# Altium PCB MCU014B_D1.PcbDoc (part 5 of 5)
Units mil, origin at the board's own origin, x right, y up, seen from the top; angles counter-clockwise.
Board outline 2300.04 x 4058 mil, 4 copper layers (TOP, GND, PWR, BOTTOM), stack 48.84 mil thick; 371 components, 238 nets, 1148 pads, 688 vias.
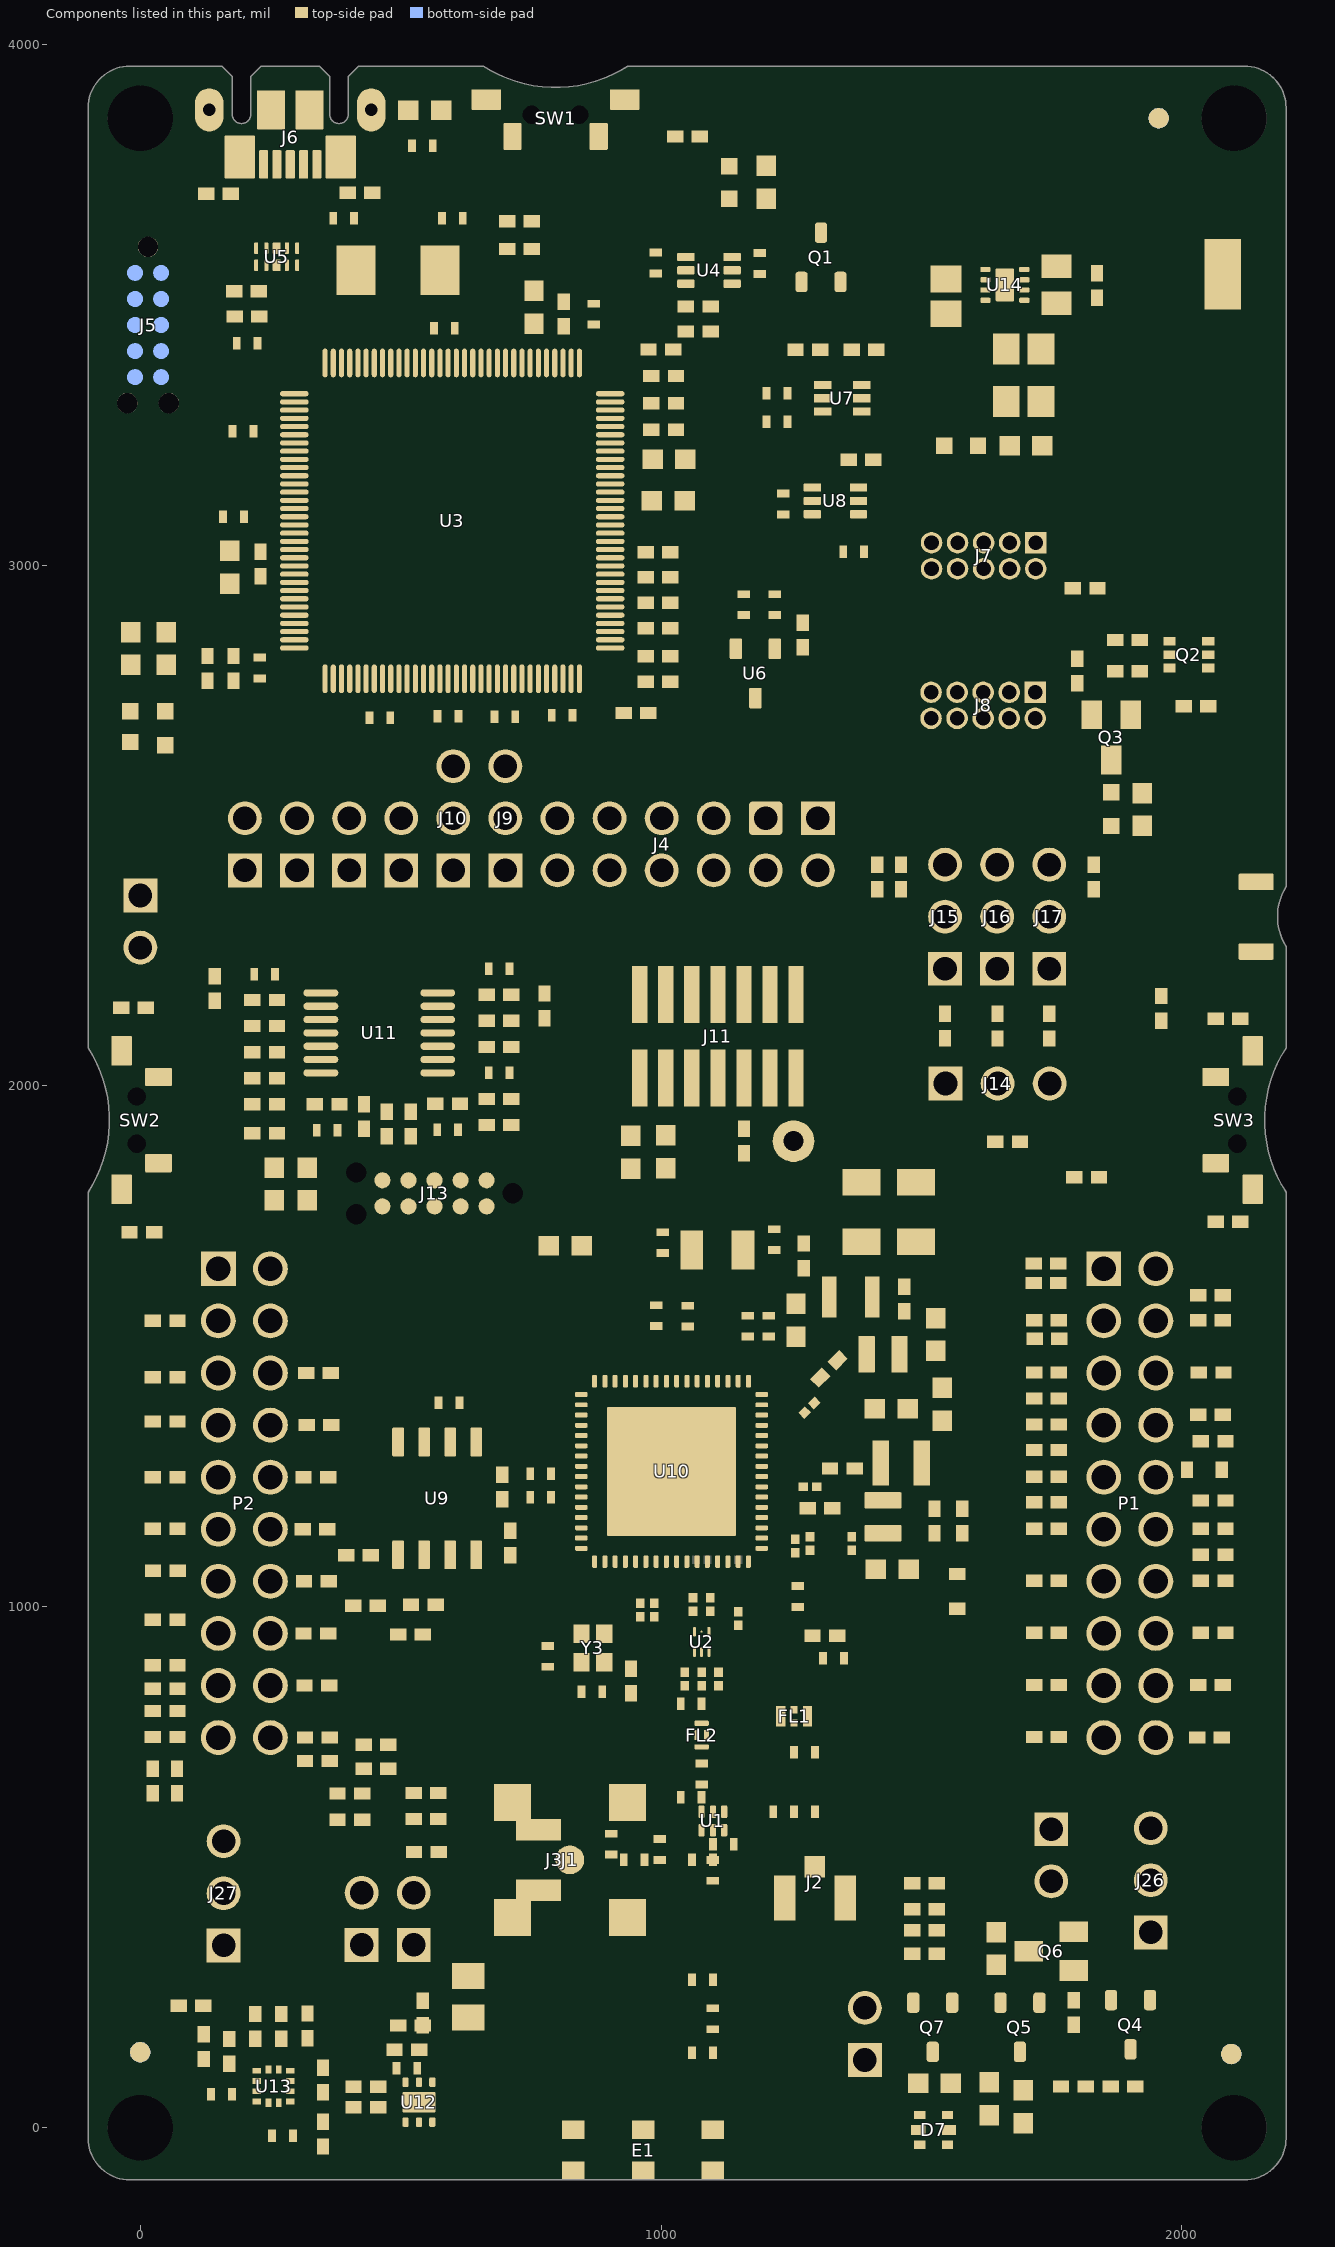
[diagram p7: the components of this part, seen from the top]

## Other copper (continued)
BOTTOM:
  pour cut-out: 729.61,-100.02 772.5,-100.02 772.5,75.2 729.61,75.2
  pour cut-out: 749.56,330.93 761.13,319.37 1068.87,319.37 1068.87,378.37 749.56,378.37
  pour cut-out: 1068.87,323.73 1077.25,332.11 1077.25,369.99 1068.87,378.37
  pour cut-out: 862.43,282.25 862.43,217.85 885.01,195.27 1183.98,195.27 1186.09,197.38 1186.09,263.32 1168.89,280.53 1080.35,280.53 1062.71,298.17 878.35,298.17
  pour cut-out: 1090.33,496.78 1120.32,466.79 1181.55,466.79 1219.5,504.74 1098.29,504.74
  pour cut-out: 1018.6,732.85 1018.6,725.94 1030.04,714.49 1211.05,714.49 1211.05,746.79 1032.54,746.79
  pour cut-out: 1329,595.38 1329,557.41 1477.45,557.41 1483.29,563.26 1483.29,594.76 1474.26,603.79 1337.41,603.79
  pour cut-out: 343.52,1718.81 343.52,1689.22 355.34,1677.4 371.61,1677.4 384.45,1690.24 384.45,1717.67 376.92,1725.19 349.9,1725.19
  pour cut-out: 1399.31,2354.95 1399.31,2325.35 1411.13,2313.53 1427.4,2313.53 1440.24,2326.37 1440.24,2353.8 1432.71,2361.33 1405.69,2361.33
  pour cut-out: 40.82,949.77 40.82,920.18 52.64,908.36 68.91,908.36 81.75,921.2 81.75,948.62 74.22,956.15 47.2,956.15
  pour cut-out: 293.71,917.28 293.71,887.68 305.53,875.86 321.81,875.86 334.64,888.7 334.64,916.13 327.12,923.66 300.09,923.66
  pour cut-out: 705.57,2688.96 705.57,2658.96 713.24,2651.28 735.89,2651.28 742.1,2657.5 742.1,2681.97 730.78,2693.3 709.91,2693.3
  pour cut-out: 601.74,2704.6 601.74,2693.15 603.14,2691.75 622.46,2691.75 624.4,2693.69 624.4,2705.18 622,2707.58 604.72,2707.58
  pour cut-out: 596,1359 596,1537 809,1750 1575,1750 1646,1679 1646,1550 1616,1520 823,1520 661,1358 594,1358
  pour cut-out: 452.71,2851.1 460.19,2851.1 460.19,2836.9 452.71,2836.9
  pour cut-out: 1087.7,3310.6 1086.15,3318.4 1081.73,3325.02 1075.11,3329.44 1067.31,3330.99 1059.51,3329.44 1052.89,3325.02 1048.47,3318.4 1046.92,3310.6 1048.47,3302.79 1052.89,3296.18 1059.51,3291.76 1067.31,3290.2 1075.11,3291.76 1081.73,3296.18 1086.15,3302.79
  pour cut-out: 152 vertices and 0 holes, not listed, extent 1872.45,1006 1927.55,1089
  pour cut-out: 2000.35,911.1 1987.07,911.1 1986.2,911.14 1985.33,911.26 1984.48,911.45 1983.65,911.71 1982.84,912.04 1982.07,912.44 1981.33,912.91 1980.64,913.44 1980,914.03 1979.41,914.68 1978.88,915.37 1978.41,916.1 1978.01,916.88 1977.67,917.68 1977.41,918.52 1977.22,919.37 1977.11,920.23 1977.07,921.1 1977.11,921.98 1977.22,922.84 1977.41,923.69 1977.67,924.52 1978.01,925.33 1978.41,926.1 1978.88,926.84 1979.18,927.25 1981.05,929.88 1982.69,932.67 1984.07,935.58 1985.2,938.61 1986.06,941.72 1986.65,944.89 1986.95,948.1 1986.98,951.33 1986.72,954.55 1986.18,957.73 1985.37,960.86 1984.29,963.9 1982.95,966.83 1981.81,968.89 1981.4,969.66 1981.06,970.46 1980.78,971.29 1980.58,972.14 1980.46,973.01 1980.41,973.88 1980.44,974.75 1980.54,975.61 1980.72,976.47 1980.97,977.3 1981.3,978.11 1981.69,978.89 1982.15,979.63 1982.67,980.33 1983.25,980.98 1983.89,981.58 1984.57,982.12 1985.3,982.6 1986.07,983.01 1986.88,983.35 1987.7,983.63 1988.55,983.83 1989.42,983.95 1990.29,984 1990.41,984 2004.56,984 2081.93,1061.37 2082.57,1061.96 2083.26,1062.49 2084,1062.96 2084.77,1063.36 2085.58,1063.7 2086.41,1063.96 2087.26,1064.15 2088.13,1064.26 2089,1064.3 2089.87,1064.26 2090.74,1064.15 2091.59,1063.96 2092.42,1063.7 2093.23,1063.36 2094,1062.96 2094.74,1062.49 2095.43,1061.96 2096.07,1061.37 2096.66,1060.73 2097.19,1060.04 2097.66,1059.3 2098.06,1058.53 2098.4,1057.72 2098.66,1056.89 2098.85,1056.04 2098.96,1055.17 2099,1054.3 2099,1009.76 2000.35,911.1
  pour cut-out: 1912.93,911.1 1887.07,911.1 1886.2,911.14 1885.33,911.26 1884.48,911.45 1883.65,911.71 1882.84,912.04 1882.07,912.44 1881.33,912.91 1880.64,913.44 1880,914.03 1879.41,914.68 1878.88,915.37 1878.41,916.1 1878.01,916.88 1877.67,917.68 1877.41,918.52 1877.22,919.37 1877.11,920.23 1877.07,921.1 1877.11,921.98 1877.22,922.84 1877.41,923.69 1877.67,924.52 1878.01,925.33 1878.41,926.1 1878.88,926.84 1879.18,927.25 1881.05,929.88 1882.69,932.67 1884.07,935.58 1885.2,938.61 1886.06,941.72 1886.65,944.89 1886.95,948.1 1886.98,951.33 1886.72,954.55 1886.18,957.73 1885.37,960.86 1884.29,963.9 1882.95,966.83 1881.81,968.89 1881.4,969.66 1881.06,970.46 1880.78,971.29 1880.58,972.14 1880.46,973.01 1880.41,973.88 1880.44,974.75 1880.54,975.61 1880.72,976.47 1880.97,977.3 1881.3,978.11 1881.69,978.89 1882.15,979.63 1882.67,980.33 1883.25,980.98 1883.89,981.58 1884.57,982.12 1885.3,982.6 1886.07,983.01 1886.88,983.35 1887.7,983.63 1888.55,983.83 1889.42,983.95 1890.29,984 1890.41,984 1909.59,984 1910.46,983.96 1911.33,983.85 1912.18,983.66 1913.01,983.4 1913.82,983.06 1914.59,982.66 1915.33,982.19 1916.02,981.66 1916.66,981.07 1917.25,980.43 1917.78,979.74 1918.25,979 1918.65,978.23 1918.99,977.42 1919.25,976.59 1919.44,975.74 1919.55,974.87 1919.59,974 1919.55,973.13 1919.44,972.26 1919.25,971.41 1918.99,970.58 1918.65,969.77 1918.25,969 1918.19,968.89 1916.66,966.05 1915.39,963.08 1914.38,960.02 1913.64,956.87 1913.18,953.68 1913,950.46 1913.1,947.23 1913.49,944.02 1914.15,940.86 1915.08,937.77 1916.28,934.78 1917.73,931.9 1919.43,929.15 1920.82,927.25 1921.32,926.54 1921.77,925.79 1922.14,925 1922.45,924.18 1922.68,923.34 1922.84,922.49 1922.92,921.62 1922.92,920.74 1922.86,919.88 1922.71,919.01 1922.49,918.17 1922.2,917.35 1921.84,916.56 1921.41,915.8 1920.91,915.08 1920.36,914.41 1919.74,913.78 1919.08,913.22 1918.37,912.71 1917.62,912.27 1916.83,911.9 1916.01,911.59 1915.17,911.36 1914.31,911.2 1913.44,911.12 1912.93,911.1
  pour cut-out: 772.5,75.2 1054,75.2 1054,55.51 1146.52,55.51 1146.52,-100 772.5,-100
  pour cut-out: 471.93,3737.96 471.93,3721.48 481.89,3711.52 493.38,3711.52 500.32,3718.45 500.32,3735.52 493.89,3741.94 475.91,3741.94
  pour cut-out: 855.47,3481.21 926.38,3410.31 927.21,3411.14 927.21,3449.21 895.21,3481.21
  pour cut-out: 752.7,732.69 1572.38,732.69 1626.28,786.59 1626.28,1102.59 1597.28,1131.59 1263.57,1131.59 1198.51,1066.52 794.35,1066.52 763.28,1097.59 763.28,1221.59 667.28,1317.59 475.28,1317.59 447.28,1289.59 447.28,1048.59 449.28,1046.59 555.28,1046.59 658.28,943.59 658.28,827.1
  pour cut-out: 312.92,3719.89 319.36,3713.45 319.36,3703.69 307.96,3703.69 298.7,3712.94
  pour cut-out: 1364.58,387.11 1364.58,372.4 1357.16,364.97 1093.98,364.97 1080.58,378.37 823.89,378.37 823.89,430.76 1320.5,431.51
  pour cut-out: 601.53,1754.19 601.53,1721.33 619.67,1703.19 633.2,1703.19 646.96,1716.95 646.96,1751.84 636.88,1761.92 609.27,1761.92
  pour cut-out: 618.75,1848.64 613.97,1843.87 625.17,1832.67 629.31,1836.8
  pour cut-out: 279.01,1933.2 279.01,1910.06 302.5,1886.58 313.73,1886.58 328.54,1901.38 328.54,1935.33 319.09,1944.78 290.6,1944.78
  pour cut-out: 1030.64,329.76 1346.3,329.77 1355.49,338.95 1355.49,359.47 1339.12,375.83 1076.71,375.83
  pour cut-out: 1336.2,702.3 1361.47,702.3 1372.62,713.45 1372.62,746.16 1336.2,746.16
  text "4" at 141.62,-60.43 h50
  text ".layer_Name" at -466,-1142 h60

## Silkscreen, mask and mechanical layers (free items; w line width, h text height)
Top Silkscreen:
  drawing of 7084 lines, arcs and shapes, not listed
  text "RESET" at 1087.18,3867.5 h30
  text "RESET" at 745.24,3720.11 h30
  text "GND" at 2038.69,3700.4 h30
  text "REV B" at 1341.44,3668.74 h30
  text "3V3" at 1526.59,3314.45 h30
  text "XDS110" at 1538.35,3161.97 h30
  text "OUT" at 1580.83,3125.63 h30
  text "CAUTION" at -77.89,3029.21 h30
  text "HOT" at -23.39,2981.11 h30
  text "SURFACE" at -81.39,2938.51 h30
  text "JTAG IN" at 1523.26,2848.71 h30
  text "VCC_BUFFER" at 1333.67,2584.19 h30 r90
  text "2" at 1535.62,2489.21 h40
  text "1" at 1640,2489.21 h40
  text "0" at 1725,2489.21 h40
  text "PD" at 1419.37,2466.31 h30
  text "FRST" at 1982.9,2457.44 h30
  text "TX" at 723.21,2296.35 h30 r90
  text "RX" at 622.21,2293.21 h30 r90
  text "5V" at 321.61,2271.91 h30 r90
  text "BRD" at 513,2266.5 h30 r90
  text "RST" at 821,2266.5 h30 r90
  text "TMS" at 927.21,2267.21 h30 r90
  text "TCK" at 1026,2266.79 h30 r90
  text "BRD" at 1322,2266.5 h30 r90
  text "TDI" at 1223.88,2266.41 h30 r90
  text "TDO" at 1120.69,2265.26 h30 r90
  text "GND" at 221.01,2251.51 h30 r90
  text "SOP" at 1464.55,2235.88 h40 r90
  text "VBAT" at 420.91,2227.21 h30 r90
  text "OPAMP EN" at 107.81,2208.21 h30 r90
  text "PU" at 1418.13,2179.33 h30
  text "(P15)" at 1820.66,2120.87 h30
  text "ET POD" at 916,1997 h30 r90
  text "SOP VCC" at 1299.54,1979.67 h30
  text "P4" at 1749.87,1714.73 h40
  text "P2" at 1972.04,1714.73 h40
  text "20" at 1913.35,1704.94 h30
  text "40" at 1827.63,1702.15 h30
  text "P1" at 79,1701 h40
  text "P3" at 277,1701 h40
  text "1" at 157,1700 h35
  text "21" at 207,1700 h35
  text "*" at 1688.11,1689.02 h30
  text "P02" at 1600.91,1664.91 h30
  text "P58" at 1599.36,1616.17 h30
  text "P18" at 2110.69,1577.16 h30
  text "*" at 1688.11,1567.97 h30
  text "*" at -17,1549 h30
  text "P01" at 1609.1,1547.44 h30
  text "P59" at 2110.19,1533.59 h30
  text "P58" at -87.26,1521.22 h30
  text "P50" at 1603.97,1496.14 h30
  text "*" at 1673.3,1436.5 h30
  text "P57" at 395,1435 h30
  text "P08" at 2106.71,1432.41 h30
  text "P04" at -87.94,1425.68 h30
  text "P17" at 1605.89,1411.79 h30
  text "*" at 1679.06,1352.14 h30
  text "P45" at 2105.31,1347.91 h30
  text "P03" at -88.6,1338.29 h30
  text "P60" at 395,1335 h30
  text "P64" at 1609.61,1329.6 h30
  text "*" at 1676.52,1245.2 h30
  text "RST" at 2113.56,1240.96 h30
  text "P58" at 386.57,1235.76 h30
  text "P61" at -84.58,1233.57 h30
  text "P21" at 1605.35,1228.92 h30
  text "*" at 1670.24,1161.86 h30
  text "*" at -13.55,1143.19 h30
  text "P59" at 385,1135 h30
  text "P18" at 1611.05,1135.04 h30
  text "P07" at 2108.11,1135.21 h30
  text "P59" at -86.29,1122.41 h30
  text "*" at 1680.67,1059.85 h30
  text "P05" at -85.24,1054.82 h30
  text "P62" at 1609.47,1035.24 h30
  text "P06" at 2110.91,1034.41 h30
  text "P63" at 390.11,1032.51 h30
  text "*" at 1665.51,966.71 h30
  text "P62" at -84.75,966.46 h30
  text "P60" at 1605.36,936.77 h30
  text "P21" at 2112.51,933.81 h30
  text "P53" at 390.64,930.95 h30
  text "P55" at 2103.91,833.71 h30
  text "P64" at 395,830 h30
  text "P01" at -67.49,828.81 h30
  text "P16" at 1605.41,827 h30
  text "P17" at 1605.41,738 h30
  text "P02" at -76.62,737.36 h30
  text "P15" at 2105.71,732.11 h30
  text "RF" at 624.83,706.53 h30
  text "11" at 1879.53,680.05 h35
  text "31" at 1785.14,676.24 h35
  text "10" at 125,666 h35
  text "30" at 215,665 h35
  text "P50" at 274.67,632.4 h30
  text "RF" at 1388.45,519.57 h30
  text "RST PU" at 1675.61,456.38 h30 r90
  text "(SCL)" at 340.79,450.17 h30 r90
  text "(SDA)" at 643.34,448.76 h30 r90
  text "LED EN" at 1311.6,150.26 h30 r90
  text "SENSORS" at 98.26,30.9 h30 r90
  text "GREEN->P02" at 1198.48,13.1 h30
  text "TEMP" at 647.32,-20.61 h30 r90
  text "RED  ->P01" at 1198.48,-34.33 h30
  text "ACC" at 127.25,-70.69 h30
  text "BLUE ->P64" at 1198.48,-81.76 h30
  text ".layer_Name" at -466,-1142 h60
Bottom Silkscreen:
  drawing of 11597 lines, arcs and shapes, not listed
  text "SimpleLink™  CC3235 Launchpad™" at 1472.95,3347.07 h90
  text "Development Kit" at 1472.95,3217.94 h90
  text "MCU014" at 467.21,3049.24 h50
  text "www.ti.com/launchpad" at 1477.14,3034.17 h90
  text "REV B" at 476.18,3007.12 h50
  text "SOP (2:0)" at 453.18,2912.19 h60
  text "XDS110 OUT" at 1747.23,2893.94 h45
  text "100  :  FLASH" at 453.19,2843.99 h60
  text "000  :  4W JTAG" at 457.59,2781.85 h60
  text "001  :  2W SWD" at 457.04,2721.9 h60
  text "010  :  FLASH/FUNC" at 457.04,2656.46 h60
  text "JTAG IN" at 1700.13,2624.28 h45
  text "VCC_BUFFER" at 1292.85,2580.18 h45 r270
  text "TX" at 691.51,2294.41 h30 r270
  text "RX" at 596.81,2286.61 h30 r270
  text "TMS" at 892,2277 h30 r270
  text "TDO" at 1088.18,2266.21 h30 r270
  text "TDI" at 1190.82,2266.08 h30 r270
  text "BRD" at 1286.21,2266.21 h30 r270
  text "BRD" at 484.21,2264.61 h30 r270
  text "5V" at 290.21,2264.21 h30 r270
  text "TCK" at 989,2262 h30 r270
  text "RST" at 792,2261 h30 r270
  text "GND" at 190.71,2254.21 h30 r270
  text "SOP" at 1425.42,2235.27 h40 r270
  text "VBAT" at 389.81,2226.61 h30 r270
  text "OPAMP EN" at 80.51,2208.91 h30 r270
  text "20" at 1954.13,1728.3 h30
  text "P1" at 110.3,1726.54 h40
  text "1" at 166.21,1727.21 h35
  text "21" at 265.21,1727.21 h35
  text "P3" at 367.66,1724.59 h40
  text "40" at 1884.34,1724.59 h30
  text "P2" at 2074.71,1719.35 h40
  text "P4" at 1787.13,1715.35 h40
  text "P02" at 1777,1632 h35
  text "P18" at 2102,1537 h35
  text "P01" at 1777,1532 h35
  text "P58" at 85.31,1529.61 h31
  text "P08" at 2105,1435 h35
  text "P57" at 403.01,1431.61 h35
  text "P17" at 1777,1432 h35
  text "P04" at 79.21,1427 h35
  text "P60" at 399.21,1340.91 h35
  text "P45" at 2106,1334 h35
  text "P64" at 1777,1331 h35
  text "P03" at 79.21,1327 h35
  text "P58" at 400.71,1243.31 h35
  text "P21" at 1777,1234 h35
  text "RST" at 2099,1234 h35
  text "P61" at 79.21,1227 h35
  text "P07" at 2102.91,1136.61 h35
  text "P59" at 399.21,1132.71 h35
  text "P18" at 1777,1133 h35
  text "P59" at 90.3,1126.83 h33
  text "P62" at 1777,1037 h35
  text "P06" at 2096,1036 h35
  text "P05" at 79.21,1027 h35
  text "P63" at 398.41,1025.21 h35
  text "P21" at 2100,934 h35
  text "P60" at 1777,933 h35
  text "P62" at 79.21,927 h35
  text "P53" at 404.31,919.01 h35
  text "P64" at 404.11,835.01 h35
  text "P55" at 2100,834 h35
  text "P16" at 1777,830 h35
  text "P01" at 79.21,827 h35
  text "P50" at 398.91,735.01 h35
  text "P15" at 2100,734 h35
  text "P17" at 1776.21,733.21 h35
  text "P02" at 79.21,727 h35
  text "30" at 271.6,635 h35
  text "11" at 1962.41,635.01 h35
  text "31" at 1868.51,634.21 h35
  text "10" at 165.6,633 h35
  text "RST PU" at 1645.62,456.38 h30 r270
  text "SDA" at 564.49,251.53 h30
  text "SCL" at 457.69,249.15 h30
  text "LED EN" at 1286.23,103.43 h30 r270
  text ".layer_Name" at -466,-1142 h60
Top Paste:
  text ".layer_Name" at -468,-1140 h60
Bottom Paste:
  text ".layer_Name" at -468,-1140 h60
Top Solder:
  text ".layer_Name" at -468,-1140 h60
Bottom Solder:
  text ".layer_Name" at -468,-1140 h60
Drill Guide:
  text ".layer_Name" at -466,-1142 h60
M1  Board Outline:
  the board outline again, w10
  text ".layer_Name" at -466,-1142 h60
M2 Board Dimensions:
  rectangle: -868.53,-701.56 -493.53,-576.56
  rectangle: -993.53,-576.56 -868.53,-451.56
  lines w7: -993.53,-576.56 6.47,-576.56 ; -868.53,-701.56 -868.53,-451.56 ; -743.53,-701.56 -743.53,-451.56 ; -493.53,-701.56 -493.53,-451.56 ; -243.53,-701.56 -243.53,-451.56 ; -993.53,-701.56 6.47,-701.56 6.47,-451.56 -993.53,-451.56 -993.53,-701.56
  text "2 PLACES" at 434.6,4117.7 h30
  text "4 PLACES" at 2352.65,3764.25 h30
  text "3 PLACES" at -656,1984.21 h60
  text ".layer_Name" at -466,-1142 h60
M3 3D STEP Top:
  pour cut-out: 1580,1720 1580,960 1155,960 1155,990 1120,1025 1035,1025 1000,990 1000,910 935,910 935,805 925,795 655,795 655,1720 1580,1720
AST:
  circle w10: c1268.67,3521.79 r8.25
  circle w10: c949.12,3865.14 r4
  circle w10: c2112.01,1778.81 r4
  circle w10: c-11.09,2085.81 r4
  circle w6: c78,346 r10
  circle w6: c1073.53,1668 r4.47
  circle w6: c178.9,2345.23 r7.21
  circle w6: c278.9,2345.23 r7.21
  circle w6: c378.9,2345.23 r7.21
  circle w6: c478.9,2345.23 r7.21
  circle w6: c578.9,2345.23 r7.21
  circle w6: c678.9,2345.23 r7.21
  circle w6: c1230.46,2584.78 r7.21
  circle w6: c1265.98,2583.27 r7.21
  circle w6: c1718.28,2755.78 r7.21
  circle w6: c1818.21,589.21 r7.21
  circle w10: c1218.4,2797.6 r8.06
  circle w6: c1073.53,1668 r4.47
  circle w6: c78,346 r10
  circle w10: c359.25,3563.2 r8.25
  circle w6: c1705.27,2156.93 r7.21
  circle w6: c1605.27,2156.93 r7.21
  circle w6: c1505.27,2156.93 r7.21
  circle w6: c1258.25,2134.13 r10
  circle w6: c1476.73,1969.77 r7.21
  circle w6: c1599.96,1908.01 r7.21
  circle w6: c1915.46,2716.43 r10
  circle w6: c1719.19,3043.01 r10
  circle w10: c1124.97,156.27 r3.29
  rectangle: 1816.76,1615.95 1883.12,1682.11
  rectangle: 116.75,1615.95 183.12,1682.11
  lines w10: -1274.5,-1223.17 5325.5,-1223.17 ; -1274.5,-1019.83 5327.5,-1019.83 ; -1274.5,-816.5 -1274.5,-1426.5 2730.5,-1426.5 5327.5,-1426.5 5327.5,-816.5 -1274,-816.5 -1274,-1426.5 301.5,-1426.5 ; 525.58,-1017.28 525.58,-816.88 ; 1116.99,-101.97 1116.99,16.14 ; 1190.5,-1426.5 1190.5,-1020.28 ; 2457.5,-1019.83 2457.5,-816.5 ; 3297.5,-1019.83 3297.5,-816.5 ; 3919.5,-1433 3919.5,-1230.17
  text "R63" at 1786.55,1813.5 h25
  text "PCB VIEWED FROM TOP SIDE" at -1211,-948.67 h60
  text "BOARD #:" at 565.5,-948.67 h60
  text ".PRJ_Title" at 1111,-948.67 h60
  text "REV:" at 2655.5,-948.67 h60
  text ".PCB_Rev" at 2947,-948.67 h60
  text "SVN REV:" at 3493.5,-948.67 h60
  text ".VersionControl_RevNumber" at 3999.5,-948.67 h60
  text "COMPONENTS MARKED 'DNP' SHOULD NOT BE POPULATED." at 1222.98,-1099.51 h35
  text "TOP ASSEMBLY DRAWING" at -1211,-1151.49 h60
  text "ASSEMBLY VARIANT:" at 1233.73,-1181.89 h35
  text ".VariantName" at 1828.34,-1185.48 h35
  text "GENERATED    :" at 1267.5,-1357.34 h60
  text ".Print_Date" at 2137,-1357.34 h60
  text ".Print_Time" at 2866,-1357.34 h60
  text "TEXAS INSTRUMENTS" at 4130.5,-1357.34 h60
ASB:
  lines w10: -1275,-1020.33 5327,-1020.33 ; -1273,-1223.67 5327,-1223.67 ; 133,-1433.5 133,-1230.67 ; 755,-1020.33 755,-817 ; 1595,-1020.33 1595,-817 ; 2862,-1427 2862,-1020.26 ; 3633.38,-1019.37 3633.38,-815.76 ; 3751,-1427 5326.5,-1427 5326.5,-817 -1275,-817 -1275,-1427 1322,-1427 5327,-1427 5327,-817
  text ".VersionControl_RevNumber" at 53,-949.17 h60
  text "SVN REV:" at 559,-949.17 h60
  text ".PCB_Rev" at 1105.5,-949.17 h60
  text "REV:" at 1397,-949.17 h60
  text "PCB VIEWED FROM BOTTOM SIDE" at 5263.5,-949.17 h60
  text ".PRJ_title" at 3062.64,-951.18 h60
  text "BOARD #:" at 3553.68,-951.18 h60
  text "COMPONENTS MARKED 'DNP' SHOULD NOT BE POPULATED." at 2838.45,-1092.34 h35
  text "BOTTOM ASSEMBLY DRAWING" at 5263.5,-1153.5 h60
  text ".VariantName" at 2175.78,-1174.74 h35
  text "ASSEMBLY VARIANT:" at 2831.29,-1181.89 h35
  text "TEXAS INSTRUMENTS" at -78,-1357.84 h60
  text ".Print_Time" at 1186.5,-1357.84 h60
  text ".Print_Date" at 1915.5,-1357.84 h60
  text "GENERATED    :" at 2785,-1357.84 h60
Route Tool Path:
  drawing of 57 lines, arcs and shapes, not listed
  text "1" at -253.7,7734.94 h70
  text "2" at 2241.97,7734.94 h70
  text "3" at 4731.31,7734.94 h70
  text "4" at 7237.98,7734.94 h70
  text "5" at 9736.97,7734.94 h70
  text "6" at 12241.97,7734.94 h70
  text "A" at -1410.03,6591.94 h70
  text "A" at 13389.97,6591.94 h70
  text "B" at -1410.03,4211.94 h70
  text "B" at 13389.97,4211.94 h70
  text "C" at -1410.03,1836.94 h70
  text "C" at 13389.97,1836.94 h70
  text "PROJECT TITLE:" at 10349.97,-24.06 h45
  text ".PRJ_Title" at 10399.97,-157.38 h70
  text "DESIGNED FOR:" at 10349.97,-325.06 h45
  text ".PRJ_Customer" at 10399.97,-465.06 h70
  text "D" at -1410.03,-533.06 h70
  text "D" at 13389.97,-533.06 h70
  text "FILE NAME:" at 10349.97,-625.06 h45
  text ".PCB_File_Name_No_Path" at 10399.97,-745.06 h70
  text "Texas Instruments (TI) and/or its licensors do not warrant the accuracy or completeness of this specification" at 5380.47,-906.9 h45
  text "ENGINEER:" at 10349.97,-915.06 h45
  text "LAYOUT BY:" at 11854.97,-915.06 h45
  text "or any information contained therein. TI and/or its licensors do not warrant that this design will meet" at 5335.48,-1019.56 h45
  text ".PRJ_Engineer" at 10399.97,-1070.05 h70
  text ".PCB_Layout" at 11905.47,-1070.05 h70
  text "the specifications, will be suitable for your application or fit for any particular purpose, or will operate in" at 5335.48,-1132.23 h45
  text ".layer_Name" at -466,-1142 h60
  text "ALTIUM DESIGNER VERSION:" at 11854.97,-1225.06 h45
  text "an implementation. TI and/or its licensors do not warrant that the design is production worthy. You should" at 5335.48,-1244.89 h45
  text "completely validate and test your design implementation to confirm the system functionality for your application." at 5380.47,-1357.56 h45
  text ".print_Scale" at 10399.97,-1358.38 h70
  text ".Application_BuildNumber" at 11905.47,-1358.38 h70
  text "1" at -253.7,-1565.06 h70
  text "2" at 2241.97,-1565.06 h70
  text "3" at 4731.31,-1565.06 h70
  text "4" at 7237.98,-1565.06 h70
  text "5" at 9736.97,-1565.06 h70
  text "6" at 11302.71,-1565.06 h70
  text "WO# : 307170-7168-1DU" at 11753.54,-1565.06 h70
M10 Fab Notes:
  drawing of 213 lines, arcs and shapes, not listed
  text "FAB NOTES :" at -1133.5,7542.43 h65
  text "1. EXPOSED COPPER ARE PRESENT AT BOARD EDGE IN ALL ELECTRICAL LAYERS AT THE LOCATION \"DETAIL A\". copper in that area must be as close to the edge as current processing allows" at -1129.88,7372.9 h65
  text "2. THE SOLDER MASK IMAGES THAT ARE THE SAME SIZE AS THE COMPONENT PADS MAY BE ENLARGED AS PER THE MANUFACTURING CAPABILITIES." at -1129.88,7214.17 h65
  text "ALL OTHER SOLDER MASK IMAGES SHALL NOT BE MODIFIED." at -936.12,7098.21 h65
  text "DESIGN INFORMATION" at 11387.49,6143.44 h60
  text "MIN. TRACK WIDTH:" at 10742.93,5963.44 h60
  text "MIL" at 11993.93,5963.44 h60
  text "6" at 11835,5962 h60
  text "4" at 11833.1,5833.96 h60
  text "MIN. CLEARANCE:" at 10742.93,5831.44 h60
  text "MIL" at 11993.93,5831.44 h60
  text "MIN. VIA PAD SIZE:" at 10742.93,5699.44 h60
  text "18" at 11809.18,5699.45 h60
  text "MIL" at 11993.93,5699.44 h60
  text "EXTERNAL" at 12288.21,5559.21 h60
  text "2 MIL" at 11437.93,5557.73 h60
  text "MINIMUM ANNULAR RING" at 10413.7,5553.45 h60
  text "PER" at 10613.7,5435.45 h60
  text "IPC-D-275 CLASS 2 LEVEL C" at 10833.7,5435.44 h60
  text "MIL, HOLES" at 12321.93,5323.16 h60
  text "+/-" at 11929.47,5322.44 h60
  text "+/-" at 12783.47,5322.44 h60
  text "REGISTRATION TOLERANCES:" at 10413.7,5317.44 h60
  text "METAL" at 11613.47,5317.44 h60
  text "5" at 12189.67,5317.45 h60
  text "3" at 13022.67,5317.45 h60
  text "MIL" at 13138.93,5317.44 h60
  text "MATERIAL:" at 10338.93,5107.98 h60
  text "FR-4 High Tg" at 11325.37,4967.65 h60
  text "FR-408" at 10759.93,4959.08 h60
  text "X" at 11171.93,4959.08 h60
  text "OTHER" at 12247.93,4959.08 h60
  text "1.28mm+/-10%" at 12644.58,4799.21 h60
  text "62 MIL (1.6mm) +/-10%" at 11080.03,4796.37 h60
  text "THICKNESS:" at 10413.7,4792.08 h60
  text "X" at 12246.86,4792.08 h60
  text "OTHER" at 12344.93,4792.08 h60
  text "TOLERANCE:" at 10413.7,4634.08 h60
  text "X" at 11253,4634.08 h60
  text "ANSI IPC-6012 TYPE 3 CLASS 2" at 11439.94,4634.08 h60
  text "OTHER +/-" at 11439.93,4478.08 h60
  text "BOW & TWIST:" at 10413.7,4321.08 h60
  text "X" at 11253,4321.08 h60
  text "ANSI IPC-6012 TYPE 3 CLASS 2" at 11439.94,4321.08 h60
  text "OTHER +/-" at 11439.93,4162.57 h60
  text "COPPER THICKNESS (FINISHED):" at 10392.46,3906.14 h60
  text "1.4MIL (1oz)" at 12644.46,3758.42 h60
  text "INNER SIGNAL:" at 11832.38,3754.14 h60
  text "X" at 12517.42,3754.14 h60
  text "1.4MIL (1oz)" at 11272.46,3753.42 h60
  text "OUTER:" at 10749.46,3749.14 h60
  text "X" at 11144,3748.5 h60
  text "DRILLING:" at 10338.93,3489.08 h60
  text "REFERENCE:" at 10413.7,3372.08 h60
  text "X" at 11061.93,3372.08 h60
  text "AS SHOWN" at 11248.93,3372.08 h60
  text "X" at 11962.93,3372.08 h60
  text "NC_DRILL FILES" at 12099.93,3372.08 h60
  text "PTH MIN COPPER THICKNESS:" at 10413.7,3214.08 h60
  text "X" at 11763.93,3214.08 h60
  text "1MIL" at 11900.93,3214.08 h60
  text "OTHER" at 12397.93,3214.08 h60
  text "BOARD FINISH:" at 10338.93,3055.08 h60
  text "SILKSCREEN:" at 10494.15,2937.08 h60
  text "X" at 11442.93,2937.08 h60
  text "TOP" at 11568.93,2937.08 h60
  text "X" at 11952.93,2937.08 h60
  text "BOTTOM" at 12079.93,2937.08 h60
  text "SILKSCREEN COLOR:" at 10494.15,2770.08 h60
  text "X" at 11441.89,2770.08 h60
  text "WHITE" at 11568.93,2770.08 h60
  text "OTHER" at 12079.93,2770.08 h60
  text "SOLDER RESIST COLOR:" at 10494.15,2600.08 h60
  text "X" at 12166.89,2445.88 h60
  text "GREEN" at 11188.93,2440.88 h60
  text "BLUE" at 11779.93,2440.88 h60
  text "OTHER" at 12317.93,2440.88 h60
  text "RED" at 12707.93,2435.88 h60
  text "IMMERSION GOLD (ENIG)" at 11399.93,2252.37 h60
  text "ENEPIG" at 12737.47,2249.08 h60
  text "SURFACE FINISH:" at 10338.93,2248.08 h60
  text "X" at 11212.98,2248.08 h60
  text "IMM. TIN/SILVER OR EQUIV" at 10668.47,2091.08 h60
  text "OTHER" at 12099.93,2091.08 h60
  text "ARRAY/PANEL:" at 10338.93,1912.08 h60
  text "CUT AND TRIM PER MECH LAYER 1" at 11399.93,1907.8 h60
  text "N.C. ROUTE" at 11399.93,1756.08 h60
  text "V. SCORE" at 12265.93,1756.08 h60
  text "X" at 11209.99,1755.17 h60
  text "CERTIFICATION:" at 10338.93,1619.08 h60
  text "MATERIALS AND WORKMANSHIP FOR ALL PCBS" at 11063.93,1619.08 h60
  text "TO MEET OR EXCEED THE REQUIREMENTS OF:" at 11063.93,1521.08 h60
  text "X" at 10690.43,1384.58 h60
  text "ANSI IPC-A-600F CLASS ->" at 10829.43,1384.58 h60
  text "X" at 12468.49,1384.58 h60
  text "2" at 12587.43,1384.58 h60
  text "1" at 12272.43,1383.08 h60
  text "3" at 12941.43,1383.08 h60
  text "X" at 10692.49,1225.08 h60
  text "UL 94V-0" at 10829.43,1225.08 h60
  text "X" at 11504.49,1225.08 h60
  text "RoHS" at 11641.43,1225.08 h60
  text "OTHER" at 12285.83,1225.08 h60
  text "PER ORDER" at 12682.89,1225.08 h60
  text "ADDITIONAL REQUIREMENTS:" at 10338.93,1084.08 h60
  text "X" at 12320.49,985.08 h60
  text "YES" at 12456.43,983.08 h60
  text "NO" at 12910.43,983.08 h60
  text "VIA TENTING:" at 11561,978 h60
  text "MICROSECTION:" at 10413.7,969.08 h60
  text "YES" at 11319.43,969.08 h60
  text "REQUIRED" at 12180.93,812.94 h60
  text "BARE BOARD ELEC. TEST:" at 10413.7,810.08 h60
  text "NONE" at 11719.43,810.08 h60
  text "X" at 12053.93,810.08 h60
  text "PER ORDER" at 12772.93,810.08 h60
  text "MANUFACTURER'S UL:" at 10413.7,653.08 h60
  text "RAIL" at 11579.43,648.8 h60
  text "METAL" at 12071.24,648.8 h60
  text "SILK" at 12582.93,648.8 h60
  text "X" at 12446.47,648.44 h60
  text ".layer_Name" at -466,-1142 h60
M11 Gerber Information:
  lines w10: -1285.53,-1231.72 5314.47,-1231.72 ; -1285.53,-1028.39 5316.47,-1028.39 ; -1285.53,-825.06 -1285.53,-1435.06 2719.47,-1435.06 5316.47,-1435.06 5316.47,-825.06 -1285.03,-825.06 -1285.03,-1435.06 290.47,-1435.06 ; 704.27,-1028.98 704.27,-826.22 ; 1179.47,-1435.06 1179.47,-1027.64 ; 2647.88,-1028.62 2647.88,-825.28 ; 3286.47,-1028.39 3286.47,-825.06 ; 3908.47,-1441.56 3908.47,-1238.72
  text ".PCB_Rev" at 2968.73,-956.1 h60
  text "ALL ARTWORK VIEWED FROM TOP SIDE" at -1222.03,-957.22 h60
  text "BOARD #:" at 747.56,-957.22 h60
  text ".PRJ_title" at 1293.06,-957.22 h60
  text "REV:" at 2702.69,-956.74 h60
  text "SVN REV:" at 3482.47,-957.22 h60
  text ".VersionControl_RevNumber" at 3988.47,-957.22 h60
  text "LAYER NAME =" at -1222.03,-1140 h60
  text "GENERATED    :" at 1256.47,-1365.89 h60
  text ".Print_Date" at 2125.97,-1365.89 h60
  text ".Print_Time" at 2854.97,-1365.89 h60
  text "TEXAS INSTRUMENTS" at 4119.47,-1365.89 h60
M12 Stackup:
  drawing of 306 lines, arcs and shapes, not listed
  text "LAYER STACKUP" at 4664.28,3466.47 h125
  text "Layer" at 3408.27,3247.73 h60
  text "Name" at 3818.18,3247.73 h60
  text "Material" at 4917.87,3247.73 h60
  text "Thickness" at 5777.64,3247.73 h60
  text "Constant" at 6427.48,3247.73 h60
  text "Board Layer Stack" at 6997.34,3247.73 h60
  text "1" at 3408.27,3127.73 h60
  text "Top Silkscreen" at 3818.18,3127.73 h60
  text "2" at 3408.27,3007.73 h60
  text "Top Solder" at 3818.18,3007.73 h60
  text "Solder Resist" at 4917.87,3007.73 h60
  text "0.80mil" at 5777.64,3007.73 h60
  text "4.1" at 6427.48,3007.73 h60
  text "3" at 3408.27,2887.73 h60
  text "TOP" at 3818.18,2887.73 h60
  text "Copper" at 4917.87,2887.73 h60
  text "1.69mil" at 5777.64,2887.73 h60
  text "4" at 3408.27,2767.73 h60
  text "Dielectric1" at 3818.18,2767.73 h60
  text "FR-4 High Tg" at 4917.87,2767.73 h60
  text "9.30mil" at 5777.64,2767.73 h60
  text "3.9" at 6427.48,2767.73 h60
  text "5" at 3408.27,2647.73 h60
  text "GND" at 3818.18,2647.73 h60
  text "Copper" at 4917.87,2647.73 h60
  text "1.42mil" at 5777.64,2647.73 h60
  text "6" at 3408.27,2527.73 h60
  text "Dielectric2" at 3818.18,2527.73 h60
  text "FR-4 High Tg" at 4917.87,2527.73 h60
  text "24.02mil" at 5777.64,2527.73 h60
  text "4.24" at 6427.48,2527.73 h60
  text "7" at 3408.27,2407.73 h60
  text "PWR" at 3818.18,2407.73 h60
  text "Copper" at 4917.87,2407.73 h60
  text "1.42mil" at 5777.64,2407.73 h60
  text "8" at 3408.27,2287.73 h60
  text "Dielectric3" at 3818.18,2287.73 h60
  text "FR-4 High Tg" at 4917.87,2287.73 h60
  text "9.30mil" at 5777.64,2287.73 h60
  text "3.9" at 6427.48,2287.73 h60
  text "9" at 3408.27,2167.73 h60
  text "BOTTOM" at 3818.18,2167.73 h60
  text "Copper" at 4917.87,2167.73 h60
  text "1.69mil" at 5777.64,2167.73 h60
  text "10" at 3408.27,2047.73 h60
  text "Bottom Solder" at 3818.18,2047.73 h60
  text "Solder Resist" at 4917.87,2047.73 h60
  text "0.80mil" at 5777.64,2047.73 h60
  text "4.1" at 6427.48,2047.73 h60
  text "11" at 3408.27,1927.73 h60
  text "Bottom Silkscreen" at 3818.18,1927.73 h60
  text "THIS IS AN IMPEDANCE CONTROLLED BOARD" at 3766.39,1661.2 h125
  text "NOTE : EXTERNAL LAYER CU THICKNESS ARE FINISHED THICKNESS AFTER PLATING." at 3528.79,1439.45 h75
  text "IMPEDANCE TABLE" at 4765.91,953.13 h125
  text "LAYER NO" at 3566.52,625.77 h70
  text "CONDUCTOR WIDTH" at 4212.04,625.77 h70
  text "SPACING" at 5289.85,625.77 h70
  text "IMPEDANCE +/-10%" at 5877.1,625.77 h70
  text "REFERENCE GND" at 7058.15,625.77 h70
  text "15 MIL" at 4499.4,356.91 h70
  text "1" at 3676.06,354.44 h70
  text "(TOP)" at 3776.06,354.44 h70
  text "GND" at 7307.37,354.44 h70
  text "50ohm" at 6124.61,351.18 h70
  text "10 MIL" at 5341.3,347.53 h70
  text ".layer_Name" at -466,-1142 h60
M13 Component Bodies Top:
  lines w3: 2138,3958 2200,3958
Drill Drawing:
  circle w10: c1913.18,6414.42 r33.33
  lines w10: 1882.23,6659.96 2718.67,6659.96 ; 1674.38,5743.78 1674.38,5852.67 1783.28,5852.67 1783.28,5743.78 1674.38,5743.78 ; 1879.84,4581.08 1946.51,4581.08 1946.51,4647.75 1879.84,4647.75 1879.84,4581.08
  lines w15: 1820.05,4386.08 9927.81,4386.08 ; 1820.05,6486.08 9927.81,6486.08 ; 2370.93,4236.08 2370.93,6636.08 ; 3068.74,4236.08 3068.74,6636.08 ; 4414.35,4236.08 4414.35,6636.08 ; 4920.22,4236.08 4920.22,6636.08 ; 5654.02,4236.08 5654.02,6636.08 ; 6723.71,4236.08 6723.71,6636.08 ; 8081.31,4236.08 8081.31,6636.08 ; 9163,4236.08 9163,6636.08 ; 1820.05,4236.08 9927.81,4236.08 9927.81,6636.08 1820.05,6636.08 1820.05,4236.08
  text "DRILL CHART :" at 1876.25,6685.24 h70
  text "Symbol" at 1910.05,6531.08 h72
  text "Hit Count" at 2415.93,6531.08 h72
  text "Finished Hole Size" at 3113.74,6531.08 h72
  text "Plated" at 4459.35,6531.08 h72
  text "Hole Type" at 4965.22,6531.08 h72
  text "Hole Length" at 5699.02,6531.08 h72
  text "Routed Path Length" at 6768.71,6531.08 h72
  text "Hole Tolerance" at 8126.31,6531.08 h72
  text "Tenting" at 9208,6531.08 h72
  text "32" at 2415.93,6381.08 h60
  text "7.87mil (0.200mm)" at 3113.74,6381.08 h60
  text "PTH" at 4459.35,6381.08 h60
  text "Round" at 4965.22,6381.08 h60
  text "-" at 5699.02,6381.08 h60
  text "-" at 6768.71,6381.08 h60
  text "4" at 2415.93,6231.08 h60
  text "7.87mil (0.200mm)" at 3113.74,6231.08 h60
  text "PTH" at 4459.35,6231.08 h60
  text "Round" at 4965.22,6231.08 h60
  text "-" at 5699.02,6231.08 h60
  text "-" at 6768.71,6231.08 h60
  text "+0.00mil/-7.87mil" at 8126.31,6231.08 h60
  text "Bottom Side" at 9208,6231.08 h60
  text "A" at 1880.96,6221.09 h66.67
  text "246" at 2415.93,6081.08 h60
  text "8.00mil (0.203mm)" at 3113.74,6081.08 h60
  text "PTH" at 4459.35,6081.08 h60
  text "Round" at 4965.22,6081.08 h60
  text "-" at 5699.02,6081.08 h60
  text "-" at 6768.71,6081.08 h60
  text "+0.00mil/-4.00mil" at 8126.31,6081.08 h60
  text "Both Sides" at 9208,6081.08 h60
  text "B" at 1880.96,6071.09 h66.67
  text "159" at 2415.93,5931.08 h60
  text "10.00mil (0.254mm)" at 3113.74,5931.08 h60
  text "PTH" at 4459.35,5931.08 h60
  text "Round" at 4965.22,5931.08 h60
  text "-" at 5699.02,5931.08 h60
  text "-" at 6768.71,5931.08 h60
  text "+0.00mil/-4.00mil" at 8126.31,5931.08 h60
  text "Both Sides" at 9208,5931.08 h60
  text "C" at 1880.96,5921.09 h66.67
  text "230" at 2415.93,5781.08 h60
  text "12.00mil (0.305mm)" at 3113.74,5781.08 h60
  text "PTH" at 4459.35,5781.08 h60
  text "Round" at 4965.22,5781.08 h60
  text "-" at 5699.02,5781.08 h60
  text "-" at 6768.71,5781.08 h60
  text "+0.00mil/-4.00mil" at 8126.31,5781.08 h60
  text "Both Sides" at 9208,5781.08 h60
  text "D" at 1880.96,5771.09 h66.67
  text "3" at 1706.11,5768.23 h60
  text "17" at 2415.93,5631.08 h60
  text "16.00mil (0.406mm)" at 3113.74,5631.08 h60
  text "PTH" at 4459.35,5631.08 h60
  text "Round" at 4965.22,5631.08 h60
  text "-" at 5699.02,5631.08 h60
  text "-" at 6768.71,5631.08 h60
  text "+0.00mil/-4.00mil" at 8126.31,5631.08 h60
  text "Both Sides" at 9208,5631.08 h60
  text "F" at 1880.96,5621.09 h66.67
  text "2" at 2415.93,5481.08 h60
  text "23.62mil (0.600mm)" at 3113.74,5481.08 h60
  text "PTH" at 4459.35,5481.08 h60
  text "Slot" at 4965.22,5481.08 h60
  text "51.18mil (1.300mm)" at 5699.02,5481.08 h60
  text "27.56mil (0.700mm)" at 6768.71,5481.08 h60
  text "+/-3.00mil" at 8126.31,5481.08 h60
  text "G" at 1880.96,5471.09 h66.67
  text "20" at 2415.93,5331.08 h60
  text "27.95mil (0.710mm)" at 3113.74,5331.08 h60
  text "PTH" at 4459.35,5331.08 h60
  text "Round" at 4965.22,5331.08 h60
  text "-" at 5699.02,5331.08 h60
  text "-" at 6768.71,5331.08 h60
  text "+/-3.00mil" at 8126.31,5331.08 h60
  text "H" at 1880.96,5321.09 h66.67
  text "6" at 2415.93,5181.08 h60
  text "35.43mil (0.900mm)" at 3113.74,5181.08 h60
  text "NPTH" at 4459.35,5181.08 h60
  text "Round" at 4965.22,5181.08 h60
  text "-" at 5699.02,5181.08 h60
  text "-" at 6768.71,5181.08 h60
  text "+/-2.00mil" at 8126.31,5181.08 h60
  text "I" at 1892.07,5171.09 h66.67
  text "1" at 2415.93,5031.08 h60
  text "37.99mil (0.965mm)" at 3113.74,5031.08 h60
  text "PTH" at 4459.35,5031.08 h60
  text "Round" at 4965.22,5031.08 h60
  text "-" at 5699.02,5031.08 h60
  text "-" at 6768.71,5031.08 h60
  text "+/-3.00mil" at 8126.31,5031.08 h60
  text "J" at 1880.96,5021.09 h66.67
  text "6" at 2415.93,4881.08 h60
  text "39.00mil (0.991mm)" at 3113.74,4881.08 h60
  text "NPTH" at 4459.35,4881.08 h60
  text "Round" at 4965.22,4881.08 h60
  text "-" at 5699.02,4881.08 h60
  text "-" at 6768.71,4881.08 h60
  text "+/-2.00mil" at 8126.31,4881.08 h60
  text "K" at 1880.96,4871.09 h66.67
  text "54" at 2415.93,4731.08 h60
  text "45.28mil (1.150mm)" at 3113.74,4731.08 h60
  text "PTH" at 4459.35,4731.08 h60
  text "Round" at 4965.22,4731.08 h60
  text "-" at 5699.02,4731.08 h60
  text "-" at 6768.71,4731.08 h60
  text "+/-3.00mil" at 8126.31,4731.08 h60
  text "M" at 1880.96,4721.09 h66.67
  text "40" at 2415.93,4581.08 h60
  text "47.24mil (1.200mm)" at 3113.74,4581.08 h60
  text "PTH" at 4459.35,4581.08 h60
  text "Round" at 4965.22,4581.08 h60
  text "-" at 5699.02,4581.08 h60
  text "-" at 6768.71,4581.08 h60
  text "4" at 2415.93,4431.08 h60
  text "125.00mil (3.175mm)" at 3113.74,4431.08 h60
  text "NPTH" at 4459.35,4431.08 h60
  text "Round" at 4965.22,4431.08 h60
  text "-" at 5699.02,4431.08 h60
  text "-" at 6768.71,4431.08 h60
  text "+/-2.00mil" at 8126.31,4431.08 h60
  text "N" at 1880.96,4421.09 h66.67
  text "821 Total" at 2415.93,4281.08 h60
  text "Slot definitions :" at 1910.05,4136.11 h60
  text "Routed Path Length" at 2942.74,4136.11 h60
  text "= Calculated from tool start centre position to tool end centre position." at 4045.41,4136.11 h60
  text "Hole Length" at 2942.74,4036.13 h60
  text "= Routed Path Length + Tool Size = Slot length as defined in the PCB layout" at 3635.54,4036.13 h60
  text "FAB" at -468,-1140 h60

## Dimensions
-13.36,4.64 to -97.09,44.4 on M10 Fab Notes
1271.96,-164 to 1342.77,-163.32 on M10 Fab Notes
2138,3958 to 2200.01,2382.86 on M2 Board Dimensions
382.14,3884.74 to 407.63,4003.92 on M2 Board Dimensions
-313.24,1934.59 to -129.03,1934.59 on M2 Board Dimensions
2120,-100 to 2200,1796 on M2 Board Dimensions
2120,-100 to 2120,3958 on M2 Board Dimensions
2120,-100 to 2200,2073.19 on M2 Board Dimensions
2216.02,3915.59 to 2364.57,3877.32 on M2 Board Dimensions
-993.53,-701.56 to 6.47,-701.56 on M2 Board Dimensions
0,3858 to -20,3958 on M2 Board Dimensions
0,0 to 2200,-20 on M2 Board Dimensions
0,0 to -100,-20 on M2 Board Dimensions
212.21,3938.31 to -100,3878 on M2 Board Dimensions
399.22,3911.52 to -100,3878 on M2 Board Dimensions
